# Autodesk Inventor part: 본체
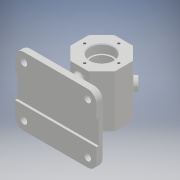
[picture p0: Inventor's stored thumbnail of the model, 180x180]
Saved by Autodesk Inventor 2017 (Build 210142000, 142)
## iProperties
Part Number: 본체
Material: 일반
Document SubType Name: Modeling
Designer: MRC
Density: 1 g/cm^3
Appearance: 기본값
Author: MRC
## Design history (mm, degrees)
sketch "스케치1"
  geometry: L1 (12.426, 30)-(30, 12.426); L2 (30, 12.426)-(30, -12.426); L3 (30, -12.426)-(12.426, -30); L4 (12.426, -30)-(-12.426, -30); L5 (-12.426, -30)-(-30, -12.426); L6 (-30, -12.426)-(-30, 12.426); L7 (-30, 12.426)-(-12.426, 30); L8 (-12.426, 30)-(12.426, 30); 2 further points
  constraints: 16 end point, 1 coincident, 1 horizontal, 17 other
  dimensions: "d0" = 30 distance from line of point (0, 0) L8
extrude "돌출1" new body sketch "스케치1" stored distance "d1" = 70; taper "d2" = 0 deg
hole "구멍1" diameter "d5" = 28; stored, may be unused: countersink angle "d9" = 90 deg, drill point angle "d11" = 0 deg; dims "d3" = 30, "d6" = 6, "d7" = 32, "d8" = 12, "d10" = 15, "d84" = 30
hole "구멍2" diameter "d15" = 50; stored, may be unused: countersink angle "d19" = 90 deg, drill point angle "d21" = 0 deg; dims "d12" = 10, "d13" = 10, "d16" = 6, "d17" = 4, "d18" = 2, "d20" = 40
sketch "스케치2"
  geometry: 2 further points
  constraints: 1 vertical alignment
  dimensions: "d22" = 23 distance of point (0, 0) point (0, 23)
hole "구멍3" sketch "스케치2" at (0, 23) diameter "d23" = 3.242; stored, may be unused: countersink angle "d27" = 90 deg, drill point angle "d29" = 118 deg; dims "d24" = 8, "d25" = 4, "d26" = 2, "d28" = 10
node "작업 평면3"
sketch "스케치3"
  geometry: L1 (0, 0)-(24.749, 24.749); L2 (0, 0)-(42.557, 0)
  constraints: 4 end point, 1 horizontal
  dimensions: "d34" = 35 distance of L1.start L1.end; "d35" = 45 deg angle of L2 L1
node "작업 평면4"
sketch "스케치4"
  geometry: C1 r 8 at (0, 0); 1 further point
  constraints: 1 centre point, 1 coincident
  dimensions: "d36" = 16 diameter of C1
extrude "돌출2" join sketch "스케치4" stored distance "d37" = 70; taper "d38" = 0 deg
hole "구멍4" diameter "d41" = 8; stored, may be unused: countersink angle "d45" = 90 deg, drill point angle "d47" = 118 deg; dims "d39" = 10, "d40" = 10, "d42" = 8, "d43" = 4, "d44" = 2, "d46" = 15.25
node "작업 평면5"
sketch "스케치5"
  geometry: L1 (55, -46)-(-55, -46); L2 (-55, -46)-(-55, 46); L3 (-55, 46)-(55, 46); L4 (55, 46)-(55, -46); L5 (55, -46)-(-55, 46); L6 (-55, -46)-(55, 46); 1 further point
  constraints: 12 end point, 2 midpoint, 2 parallel, 1 horizontal, 1 perpendicular
  dimensions: "d49" = 110 distance of L2.end L3.end; "d50" = 92 distance of L1.end L2.end
extrude "돌출3" join sketch "스케치5" distance "d51" = 10; taper "d52" = 0 deg
sketch "스케치6"
  geometry: L1 (0, 20)-(0, -20); L2 (-6, 20)-(-6, -20); L3 (6, -20)-(6, 20); A1 r 6 centre (0, 20) between (6, 20) and (-6, 20); A2 r 6 centre (0, -20) between (-6, -20) and (6, -20); 1 further point
  constraints: 8 end point, 4 point on circle, 4 tangent, 2 centre point, 1 midpoint, 1 parallel, 1 vertical
  dimensions: "d53" = 20 distance of point (0, 0) L1.end; "d54" = 12 diameter of A2
extrude "돌출4" join sketch "스케치6" stored distance "d55" = 10; taper "d56" = 0 deg
fillet "모깎기1" dims "d57" = 12
sketch "스케치7"
  geometry: L1 (-55, -34)-(-55, 34) reference; L2 (-43, 46)-(43, 46) reference; L3 (55, 34)-(55, -34) reference; L4 (43, -46)-(-43, -46) reference; A1 r 12 centre (-43, -34) between (-55, -34) and (-43, -46) reference; A2 r 12 centre (-43, 34) between (-43, 46) and (-55, 34) reference; A3 r 12 centre (43, 34) between (55, 34) and (43, 46) reference; A4 r 12 centre (43, -34) between (43, -46) and (55, -34) reference; 5 further points
  constraints: 4 coincident
hole "구멍5" sketch "스케치7" at (-43, 34), (-43, -34), (43, -34), (43, 34) diameter "d58" = 9; stored, may be unused: countersink angle "d62" = 90 deg, drill point angle "d64" = 118 deg; dims "d59" = 8, "d60" = 4, "d61" = 2, "d63" = 15.25
sketch "스케치8"
  geometry: L1 (18, 3)-(50, 3); L2 (50, 3)-(50, 0); L3 (50, 0)-(18, 0); L4 (18, 0)-(18, 3); L5 (68, 10)-(68, 0) reference; L6 (0, 10)-(68, 10) reference; L7 (0, 0)-(0, 10) reference; L8 (68, 0)-(0, 0) reference; L9 (68, 0)-(0, 0) reference; 3 further points
  constraints: 8 end point, 4 midpoint, 2 parallel, 1 horizontal, 1 perpendicular, 1 vertical alignment
  dimensions: "d65" = 32 distance of L2.end L3.end; "d66" = 3 distance of L1.end L2.end
extrude "돌출5" cut sketch "스케치8" stored distance "d67" = 10; taper "d68" = 0 deg
fillet "모깎기2" dims "d69" = 3
fillet "모깎기3" dims "d70" = 0.3
fillet "모깎기4" dims "d71" = 3
fillet "모깎기5" dims "d72" = 1
chamfer "모따기1" distance "d73" = 1; stored, may be unused: second distance "d74" = 2, angle "d75" = 45 deg
chamfer "모따기2" distance "d76" = 1; stored, may be unused: second distance "d77" = 2, angle "d78" = 45 deg
fillet "모깎기6" dims "d79" = 3
sketch "스케치9"
  geometry: 2 further points
  constraints: 1 coincident, 1 other
feature "엠보싱1" sketch "스케치9" dims "d0" = 30, "d80" = 0.5, "d81" = 0
node "솔리드1"
mirror "미러1"
pattern_circular "원형 패턴1" dims angle "d31" = 360 deg
mirror "미러2"
node "작업 평면1"
node "작업 평면2"
node "투영된 루프1"
node "투영된 루프2"
other parameters: "d33" = -35, "d48" = -62
